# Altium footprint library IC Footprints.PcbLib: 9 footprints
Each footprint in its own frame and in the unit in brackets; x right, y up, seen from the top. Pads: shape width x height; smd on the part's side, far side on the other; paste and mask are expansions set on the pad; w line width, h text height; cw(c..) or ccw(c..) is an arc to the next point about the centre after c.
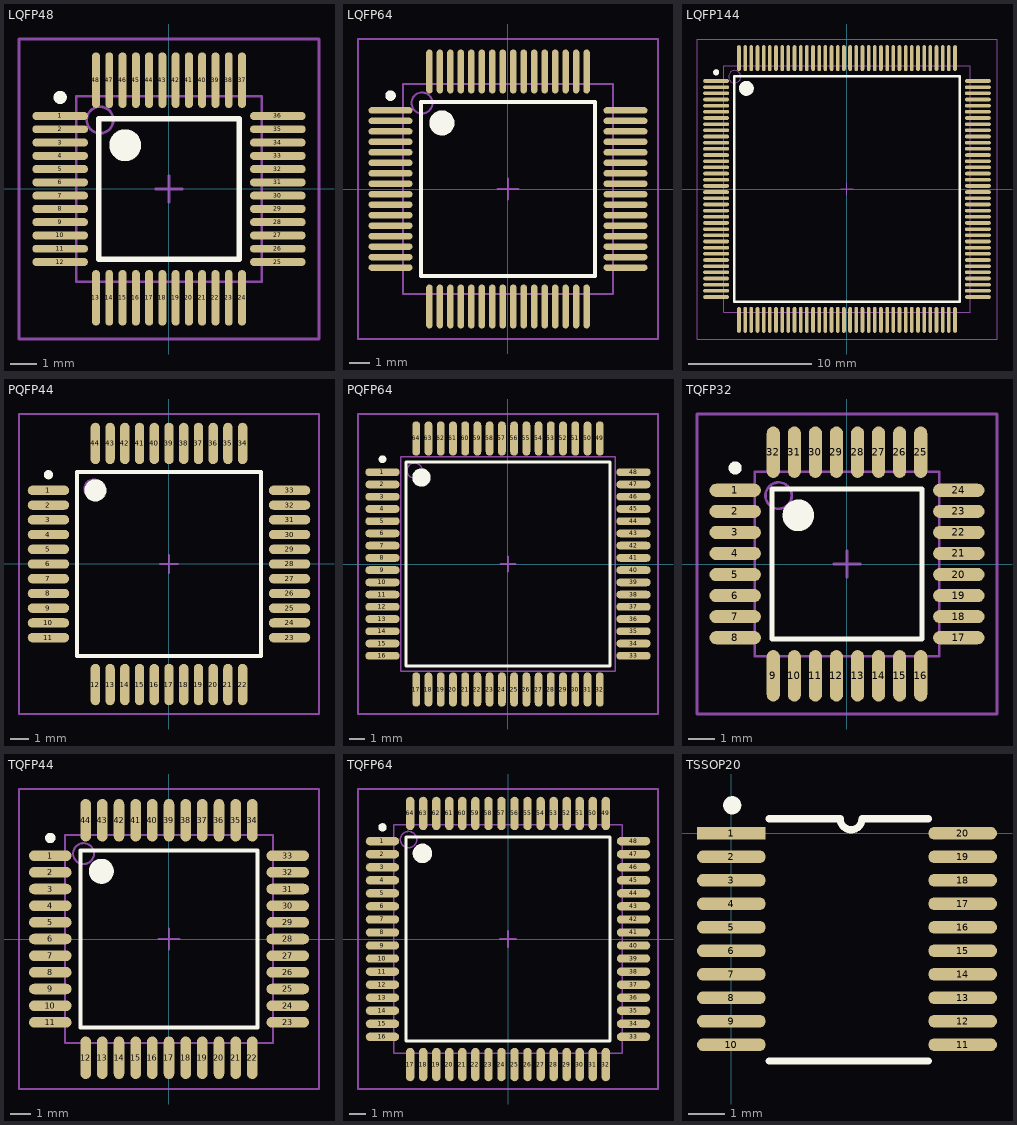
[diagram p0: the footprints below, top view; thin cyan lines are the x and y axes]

## LQFP48 [mm]
height 1.4
pads (48):
  oval 2.1x0.3 smd: 1(-4.1,2.75) 2(-4.1,2.25) 3(-4.1,1.75) 4(-4.1,1.25) 5(-4.1,0.75) 6(-4.1,0.25) 7(-4.1,-0.25) 8(-4.1,-0.75) 9(-4.1,-1.25) 10(-4.1,-1.75) 11(-4.1,-2.25) 12(-4.1,-2.75) 25(4.1,-2.75) 26(4.1,-2.25) 27(4.1,-1.75) 28(4.1,-1.25) 29(4.1,-0.75) 30(4.1,-0.25) 31(4.1,0.25) 32(4.1,0.75) 33(4.1,1.25) 34(4.1,1.75) 35(4.1,2.25) 36(4.1,2.75)
  oval 0.3x2.1 smd: 13(-2.75,-4.1) 14(-2.25,-4.1) 15(-1.75,-4.1) 16(-1.25,-4.1) 17(-0.75,-4.1) 18(-0.25,-4.1) 19(0.25,-4.1) 20(0.75,-4.1) 21(1.25,-4.1) 22(1.75,-4.1) 23(2.25,-4.1) 24(2.75,-4.1) 37(2.75,4.1) 38(2.25,4.1) 39(1.75,4.1) 40(1.25,4.1) 41(0.75,4.1) 42(0.25,4.1) 43(-0.25,4.1) 44(-0.75,4.1) 45(-1.25,4.1) 46(-1.75,4.1) 47(-2.25,4.1) 48(-2.75,4.1)
Top Overlay:
  circle w0.25: c-4.1,3.45 r0.125
  circle w0.6: c-1.65,1.65 r0.3
  lines w0.203: -2.65,-2.65 -2.65,2.65 2.65,2.65 2.65,-2.65 -2.65,-2.65
Mechanical 13:
  circle w0.1: c-2.6,2.6 r0.5
  lines w0.1: -3.5,-3.5 -3.5,3.5 3.5,3.5 3.5,-3.5 -3.5,-3.5
Mechanical 15:
  lines w0.1: -0.5,0 0.5,0 ; 0,-0.5 0,0.5 ; -5.65,-5.65 -5.65,5.65 5.65,5.65 5.65,-5.65 -5.65,-5.65

## LQFP64 [mm]
height 1.4
pads (64):
  oval 2.1x0.3 smd: 1(-5.6,3.75) 2(-5.6,3.25) 3(-5.6,2.75) 4(-5.6,2.25) 5(-5.6,1.75) 6(-5.6,1.25) 7(-5.6,0.75) 8(-5.6,0.25) 9(-5.6,-0.25) 10(-5.6,-0.75) 11(-5.6,-1.25) 12(-5.6,-1.75) 13(-5.6,-2.25) 14(-5.6,-2.75) 15(-5.6,-3.25) 16(-5.6,-3.75) 33(5.6,-3.75) 34(5.6,-3.25) 35(5.6,-2.75) 36(5.6,-2.25) 37(5.6,-1.75) 38(5.6,-1.25) 39(5.6,-0.75) 40(5.6,-0.25) 41(5.6,0.25) 42(5.6,0.75) 43(5.6,1.25) 44(5.6,1.75) 45(5.6,2.25) 46(5.6,2.75) 47(5.6,3.25) 48(5.6,3.75)
  oval 0.3x2.1 smd: 17(-3.75,-5.6) 18(-3.25,-5.6) 19(-2.75,-5.6) 20(-2.25,-5.6) 21(-1.75,-5.6) 22(-1.25,-5.6) 23(-0.75,-5.6) 24(-0.25,-5.6) 25(0.25,-5.6) 26(0.75,-5.6) 27(1.25,-5.6) 28(1.75,-5.6) 29(2.25,-5.6) 30(2.75,-5.6) 31(3.25,-5.6) 32(3.75,-5.6) 49(3.75,5.6) 50(3.25,5.6) 51(2.75,5.6) 52(2.25,5.6) 53(1.75,5.6) 54(1.25,5.6) 55(0.75,5.6) 56(0.25,5.6) 57(-0.25,5.6) 58(-0.75,5.6) 59(-1.25,5.6) 60(-1.75,5.6) 61(-2.25,5.6) 62(-2.75,5.6) 63(-3.25,5.6) 64(-3.75,5.6)
Top Overlay:
  circle w0.6: c-3.15,3.15 r0.3
  circle w0.25: c-5.6,4.45 r0.125
  lines w0.203: -4.15,-4.15 4.15,-4.15 4.15,4.15 -4.15,4.15 -4.15,-4.15
Mechanical 13:
  circle w0.1: c-4.1,4.1 r0.5
  lines w0.1: -5,-5 5,-5 5,5 -5,5 -5,-5
Mechanical 15:
  lines w0.1: -0.5,0 0.5,0 ; 0,-0.5 0,0.5 ; -7.15,-7.15 7.15,-7.15 7.15,7.15 -7.15,7.15 -7.15,-7.15

## LQFP144 [mm] "144-Pin Thin Quad Flat Pack 0.5 mm Pitch, IPC Low Density"
height 1.6
pads (144):
  oval 2.1x0.3 smd: 1(-10.6,8.75) 2(-10.6,8.25) 3(-10.6,7.75) 4(-10.6,7.25) 5(-10.6,6.75) 6(-10.6,6.25) 7(-10.6,5.75) 8(-10.6,5.25) 9(-10.6,4.75) 10(-10.6,4.25) 11(-10.6,3.75) 12(-10.6,3.25) 13(-10.6,2.75) 14(-10.6,2.25) 15(-10.6,1.75) 16(-10.6,1.25) 17(-10.6,0.75) 18(-10.6,0.25) 19(-10.6,-0.25) 20(-10.6,-0.75) 21(-10.6,-1.25) 22(-10.6,-1.75) 23(-10.6,-2.25) 24(-10.6,-2.75) 25(-10.6,-3.25) 26(-10.6,-3.75) 27(-10.6,-4.25) 28(-10.6,-4.75) 29(-10.6,-5.25) 30(-10.6,-5.75) 31(-10.6,-6.25) 32(-10.6,-6.75) 33(-10.6,-7.25) 34(-10.6,-7.75) 35(-10.6,-8.25) 36(-10.6,-8.75) 73(10.6,-8.75) 74(10.6,-8.25) 75(10.6,-7.75) 76(10.6,-7.25) 77(10.6,-6.75) 78(10.6,-6.25) 79(10.6,-5.75) 80(10.6,-5.25) 81(10.6,-4.75) 82(10.6,-4.25) 83(10.6,-3.75) 84(10.6,-3.25) 85(10.6,-2.75) 86(10.6,-2.25) 87(10.6,-1.75) 88(10.6,-1.25) 89(10.6,-0.75) 90(10.6,-0.25) 91(10.6,0.25) 92(10.6,0.75) 93(10.6,1.25) 94(10.6,1.75) 95(10.6,2.25) 96(10.6,2.75) 97(10.6,3.25) 98(10.6,3.75) 99(10.6,4.25) 100(10.6,4.75) 101(10.6,5.25) 102(10.6,5.75) 103(10.6,6.25) 104(10.6,6.75) 105(10.6,7.25) 106(10.6,7.75) 107(10.6,8.25) 108(10.6,8.75)
  oval 0.3x2.1 smd: 37(-8.75,-10.6) 38(-8.25,-10.6) 39(-7.75,-10.6) 40(-7.25,-10.6) 41(-6.75,-10.6) 42(-6.25,-10.6) 43(-5.75,-10.6) 44(-5.25,-10.6) 45(-4.75,-10.6) 46(-4.25,-10.6) 47(-3.75,-10.6) 48(-3.25,-10.6) 49(-2.75,-10.6) 50(-2.25,-10.6) 51(-1.75,-10.6) 52(-1.25,-10.6) 53(-0.75,-10.6) 54(-0.25,-10.6) 55(0.25,-10.6) 56(0.75,-10.6) 57(1.25,-10.6) 58(1.75,-10.6) 59(2.25,-10.6) 60(2.75,-10.6) 61(3.25,-10.6) 62(3.75,-10.6) 63(4.25,-10.6) 64(4.75,-10.6) 65(5.25,-10.6) 66(5.75,-10.6) 67(6.25,-10.6) 68(6.75,-10.6) 69(7.25,-10.6) 70(7.75,-10.6) 71(8.25,-10.6) 72(8.75,-10.6) 109(8.75,10.6) 110(8.25,10.6) 111(7.75,10.6) 112(7.25,10.6) 113(6.75,10.6) 114(6.25,10.6) 115(5.75,10.6) 116(5.25,10.6) 117(4.75,10.6) 118(4.25,10.6) 119(3.75,10.6) 120(3.25,10.6) 121(2.75,10.6) 122(2.25,10.6) 123(1.75,10.6) 124(1.25,10.6) 125(0.75,10.6) 126(0.25,10.6) 127(-0.25,10.6) 128(-0.75,10.6) 129(-1.25,10.6) 130(-1.75,10.6) 131(-2.25,10.6) 132(-2.75,10.6) 133(-3.25,10.6) 134(-3.75,10.6) 135(-4.25,10.6) 136(-4.75,10.6) 137(-5.25,10.6) 138(-5.75,10.6) 139(-6.25,10.6) 140(-6.75,10.6) 141(-7.25,10.6) 142(-7.75,10.6) 143(-8.25,10.6) 144(-8.75,10.6)
Top Overlay:
  circle w0.25: c-10.6,9.45 r0.125
  circle w0.6: c-8.15,8.15 r0.3
  lines w0.203: -9.15,-9.15 -9.15,9.15 9.15,9.15 9.15,-9.15 -9.15,-9.15
Mechanical 13:
  circle w0.1: c-9.1,9.1 r0.5
  lines w0.1: -10,-10 -10,10 10,10 10,-10 -10,-10
Mechanical 15:
  lines w0.1: -0.5,0 0.5,0 ; 0,-0.5 0,0.5 ; -12.15,-12.15 -12.15,12.15 12.15,12.15 12.15,-12.15 -12.15,-12.15
3D body: height 1.6, standoff 0, extent -10,-10 10,10

## PQFP44 [mm] "QFP, 44-Leads, Body 10x10mm, Pitch 0.8mm, IPC Low Density"
height 2.5
pads (44):
  oval 2.25x0.508 smd: 1(-6.55,4) 2(-6.55,3.2) 3(-6.55,2.4) 4(-6.55,1.6) 5(-6.55,0.8) 6(-6.55,0) 7(-6.55,-0.8) 8(-6.55,-1.6) 9(-6.55,-2.4) 10(-6.55,-3.2) 11(-6.55,-4) 23(6.55,-4) 24(6.55,-3.2) 25(6.55,-2.4) 26(6.55,-1.6) 27(6.55,-0.8) 28(6.55,0) 29(6.55,0.8) 30(6.55,1.6) 31(6.55,2.4) 32(6.55,3.2) 33(6.55,4)
  oval 0.508x2.25 smd: 12(-4,-6.55) 13(-3.2,-6.55) 14(-2.4,-6.55) 15(-1.6,-6.55) 16(-0.8,-6.55) 17(0,-6.55) 18(0.8,-6.55) 19(1.6,-6.55) 20(2.4,-6.55) 21(3.2,-6.55) 22(4,-6.55) 34(4,6.55) 35(3.2,6.55) 36(2.4,6.55) 37(1.6,6.55) 38(0.8,6.55) 39(0,6.55) 40(-0.8,6.55) 41(-1.6,6.55) 42(-2.4,6.55) 43(-3.2,6.55) 44(-4,6.55)
Top Overlay:
  circle w0.25: c-6.55,4.85 r0.125
  circle w0.6: c-4,4 r0.3
  lines w0.2: -5,-5 -5,5 5,5 5,-5 -5,-5
Mechanical 13:
  circle w0.1: c-4.1,4.1 r0.5
  lines w0.1: -5,-5 -5,5 5,5 5,-5 -5,-5
Mechanical 15:
  lines w0.1: -0.5,0 0.5,0 ; 0,-0.5 0,0.5 ; -8.15,-8.15 -8.15,8.15 8.15,8.15 8.15,-8.15 -8.15,-8.15
3D body: height 2.5, standoff 0, extent -5,-5 5,5

## PQFP64 [mm] "QFP, 64-Leads, Body 14x14mm, Pitch 0.8mm, IPC Low Density"
height 3.4
pads (64):
  oval 2.25x0.508 smd: 1(-8.2,6) 2(-8.2,5.2) 3(-8.2,4.4) 4(-8.2,3.6) 5(-8.2,2.8) 6(-8.2,2) 7(-8.2,1.2) 8(-8.2,0.4) 9(-8.2,-0.4) 10(-8.2,-1.2) 11(-8.2,-2) 12(-8.2,-2.8) 13(-8.2,-3.6) 14(-8.2,-4.4) 15(-8.2,-5.2) 16(-8.2,-6) 33(8.2,-6) 34(8.2,-5.2) 35(8.2,-4.4) 36(8.2,-3.6) 37(8.2,-2.8) 38(8.2,-2) 39(8.2,-1.2) 40(8.2,-0.4) 41(8.2,0.4) 42(8.2,1.2) 43(8.2,2) 44(8.2,2.8) 45(8.2,3.6) 46(8.2,4.4) 47(8.2,5.2) 48(8.2,6)
  oval 0.508x2.25 smd: 17(-6,-8.2) 18(-5.2,-8.2) 19(-4.4,-8.2) 20(-3.6,-8.2) 21(-2.8,-8.2) 22(-2,-8.2) 23(-1.2,-8.2) 24(-0.4,-8.2) 25(0.4,-8.2) 26(1.2,-8.2) 27(2,-8.2) 28(2.8,-8.2) 29(3.6,-8.2) 30(4.4,-8.2) 31(5.2,-8.2) 32(6,-8.2) 49(6,8.2) 50(5.2,8.2) 51(4.4,8.2) 52(3.6,8.2) 53(2.8,8.2) 54(2,8.2) 55(1.2,8.2) 56(0.4,8.2) 57(-0.4,8.2) 58(-1.2,8.2) 59(-2,8.2) 60(-2.8,8.2) 61(-3.6,8.2) 62(-4.4,8.2) 63(-5.2,8.2) 64(-6,8.2)
Top Overlay:
  circle w0.6: c-5.65,5.65 r0.3
  circle w0.25: c-8.2,6.85 r0.125
  lines w0.2: -6.65,-6.65 6.65,-6.65 6.65,6.65 -6.65,6.65 -6.65,-6.65
Mechanical 13:
  circle w0.1: c-6.1,6.1 r0.5
  lines w0.1: -7,-7 7,-7 7,7 -7,7 -7,-7
Mechanical 15:
  lines w0.1: -0.5,0 0.5,0 ; 0,-0.5 0,0.5 ; -9.8,-9.8 9.8,-9.8 9.8,9.8 -9.8,9.8 -9.8,-9.8
3D body: height 3.4, standoff 0, extent -7,-7 7,7

## TQFP32 [mm] "Thin QFP, 32-Leads, Body 7x7mm, Pitch 0.8mm, IPC Low Density"
height 1.2
pads (32):
  oval 1.95x0.5 smd: 1(-4.25,2.8) 2(-4.25,2) 3(-4.25,1.2) 4(-4.25,0.4) 5(-4.25,-0.4) 6(-4.25,-1.2) 7(-4.25,-2) 8(-4.25,-2.8) 17(4.25,-2.8) 18(4.25,-2) 19(4.25,-1.2) 20(4.25,-0.4) 21(4.25,0.4) 22(4.25,1.2) 23(4.25,2) 24(4.25,2.8)
  oval 0.5x1.95 smd: 9(-2.8,-4.25) 10(-2,-4.25) 11(-1.2,-4.25) 12(-0.4,-4.25) 13(0.4,-4.25) 14(1.2,-4.25) 15(2,-4.25) 16(2.8,-4.25) 25(2.8,4.25) 26(2,4.25) 27(1.2,4.25) 28(0.4,4.25) 29(-0.4,4.25) 30(-1.2,4.25) 31(-2,4.25) 32(-2.8,4.25)
Top Overlay:
  circle w0.25: c-4.25,3.65 r0.125
  circle w0.6: c-1.85,1.85 r0.3
  lines w0.2: -2.85,-2.85 -2.85,2.85 2.85,2.85 2.85,-2.85 -2.85,-2.85
Mechanical 13:
  circle w0.1: c-2.6,2.6 r0.5
  lines w0.1: -3.5,-3.5 -3.5,3.5 3.5,3.5 3.5,-3.5 -3.5,-3.5
Mechanical 15:
  lines w0.1: -0.5,0 0.5,0 ; 0,-0.5 0,0.5 ; -5.7,-5.7 -5.7,5.7 5.7,5.7 5.7,-5.7 -5.7,-5.7
3D body: height 1.2, standoff 0, extent -3.5,-3.5 3.5,3.5

## TQFP44 [mm] "Thin QFP, 44-Leads, Body 10x10mm, Pitch 0.8mm, IPC Low Density"
height 1.2
pads (44):
  oval 2.05x0.508 smd: 1(-5.7,4) 2(-5.7,3.2) 3(-5.7,2.4) 4(-5.7,1.6) 5(-5.7,0.8) 6(-5.7,0) 7(-5.7,-0.8) 8(-5.7,-1.6) 9(-5.7,-2.4) 10(-5.7,-3.2) 11(-5.7,-4) 23(5.7,-4) 24(5.7,-3.2) 25(5.7,-2.4) 26(5.7,-1.6) 27(5.7,-0.8) 28(5.7,0) 29(5.7,0.8) 30(5.7,1.6) 31(5.7,2.4) 32(5.7,3.2) 33(5.7,4)
  oval 0.508x2.05 smd: 12(-4,-5.7) 13(-3.2,-5.7) 14(-2.4,-5.7) 15(-1.6,-5.7) 16(-0.8,-5.7) 17(0,-5.7) 18(0.8,-5.7) 19(1.6,-5.7) 20(2.4,-5.7) 21(3.2,-5.7) 22(4,-5.7) 34(4,5.7) 35(3.2,5.7) 36(2.4,5.7) 37(1.6,5.7) 38(0.8,5.7) 39(0,5.7) 40(-0.8,5.7) 41(-1.6,5.7) 42(-2.4,5.7) 43(-3.2,5.7) 44(-4,5.7)
Top Overlay:
  circle w0.25: c-5.7,4.85 r0.125
  circle w0.6: c-3.25,3.25 r0.3
  lines w0.2: -4.25,-4.25 -4.25,4.25 4.25,4.25 4.25,-4.25 -4.25,-4.25
Mechanical 13:
  circle w0.1: c-4.1,4.1 r0.5
  lines w0.1: -5,-5 -5,5 5,5 5,-5 -5,-5
Mechanical 15:
  lines w0.1: -0.5,0 0.5,0 ; 0,-0.5 0,0.5 ; -7.2,-7.2 -7.2,7.2 7.2,7.2 7.2,-7.2 -7.2,-7.2
3D body: height 1.2, standoff 0, extent -5,-5 5,5

## TQFP64 [mm] "Thin QFP, 64-Leads, Body 14x14mm, Pitch 0.8mm, IPC Low Density"
height 1.2
pads (64):
  oval 2.05x0.508 smd: 1(-7.7,6) 2(-7.7,5.2) 3(-7.7,4.4) 4(-7.7,3.6) 5(-7.7,2.8) 6(-7.7,2) 7(-7.7,1.2) 8(-7.7,0.4) 9(-7.7,-0.4) 10(-7.7,-1.2) 11(-7.7,-2) 12(-7.7,-2.8) 13(-7.7,-3.6) 14(-7.7,-4.4) 15(-7.7,-5.2) 16(-7.7,-6) 33(7.7,-6) 34(7.7,-5.2) 35(7.7,-4.4) 36(7.7,-3.6) 37(7.7,-2.8) 38(7.7,-2) 39(7.7,-1.2) 40(7.7,-0.4) 41(7.7,0.4) 42(7.7,1.2) 43(7.7,2) 44(7.7,2.8) 45(7.7,3.6) 46(7.7,4.4) 47(7.7,5.2) 48(7.7,6)
  oval 0.508x2.05 smd: 17(-6,-7.7) 18(-5.2,-7.7) 19(-4.4,-7.7) 20(-3.6,-7.7) 21(-2.8,-7.7) 22(-2,-7.7) 23(-1.2,-7.7) 24(-0.4,-7.7) 25(0.4,-7.7) 26(1.2,-7.7) 27(2,-7.7) 28(2.8,-7.7) 29(3.6,-7.7) 30(4.4,-7.7) 31(5.2,-7.7) 32(6,-7.7) 49(6,7.7) 50(5.2,7.7) 51(4.4,7.7) 52(3.6,7.7) 53(2.8,7.7) 54(2,7.7) 55(1.2,7.7) 56(0.4,7.7) 57(-0.4,7.7) 58(-1.2,7.7) 59(-2,7.7) 60(-2.8,7.7) 61(-3.6,7.7) 62(-4.4,7.7) 63(-5.2,7.7) 64(-6,7.7)
Top Overlay:
  circle w0.25: c-7.7,6.85 r0.125
  circle w0.6: c-5.25,5.25 r0.3
  lines w0.2: -6.25,-6.25 -6.25,6.25 6.25,6.25 6.25,-6.25 -6.25,-6.25
Mechanical 13:
  circle w0.1: c-6.1,6.1 r0.5
  lines w0.1: -7,-7 -7,7 7,7 7,-7 -7,-7
Mechanical 15:
  lines w0.1: -0.5,0 0.5,0 ; 0,-0.5 0,0.5 ; -9.2,-9.2 -9.2,9.2 9.2,9.2 9.2,-9.2 -9.2,-9.2
3D body: height 1.2, standoff 0, extent -7,-7 7,7

## TSSOP20 [mm] "20-pin, 4.40 mm body, 0.65 mm pitch"
height 1.1
pads (20):
  rect 1.9x0.356 smd: 1(0,0)
  oval 1.9x0.356 smd: 2(0,-0.65) 3(0,-1.3) 4(0,-1.95) 5(0,-2.6) 6(0,-3.25) 7(0,-3.9) 8(0,-4.55) 9(0,-5.2) 10(0,-5.85) 11(6.4,-5.85) 12(6.4,-5.2) 13(6.4,-4.55) 14(6.4,-3.9) 15(6.4,-3.25) 16(6.4,-2.6) 17(6.4,-1.95) 18(6.4,-1.3) 19(6.4,-0.65) 20(6.4,0)
Top Overlay:
  circle w0.25: c0.025,0.775 r0.125
  lines w0.2: 3.01,0.4 ccw(c3.313,0.4) 3.615,0.4
  lines w0.203: 1.05,-6.3 5.45,-6.3 ; 1.05,0.4 1.525,0.4 2.475,0.4 2.95,0.4 ; 3.65,0.4 5.45,0.4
